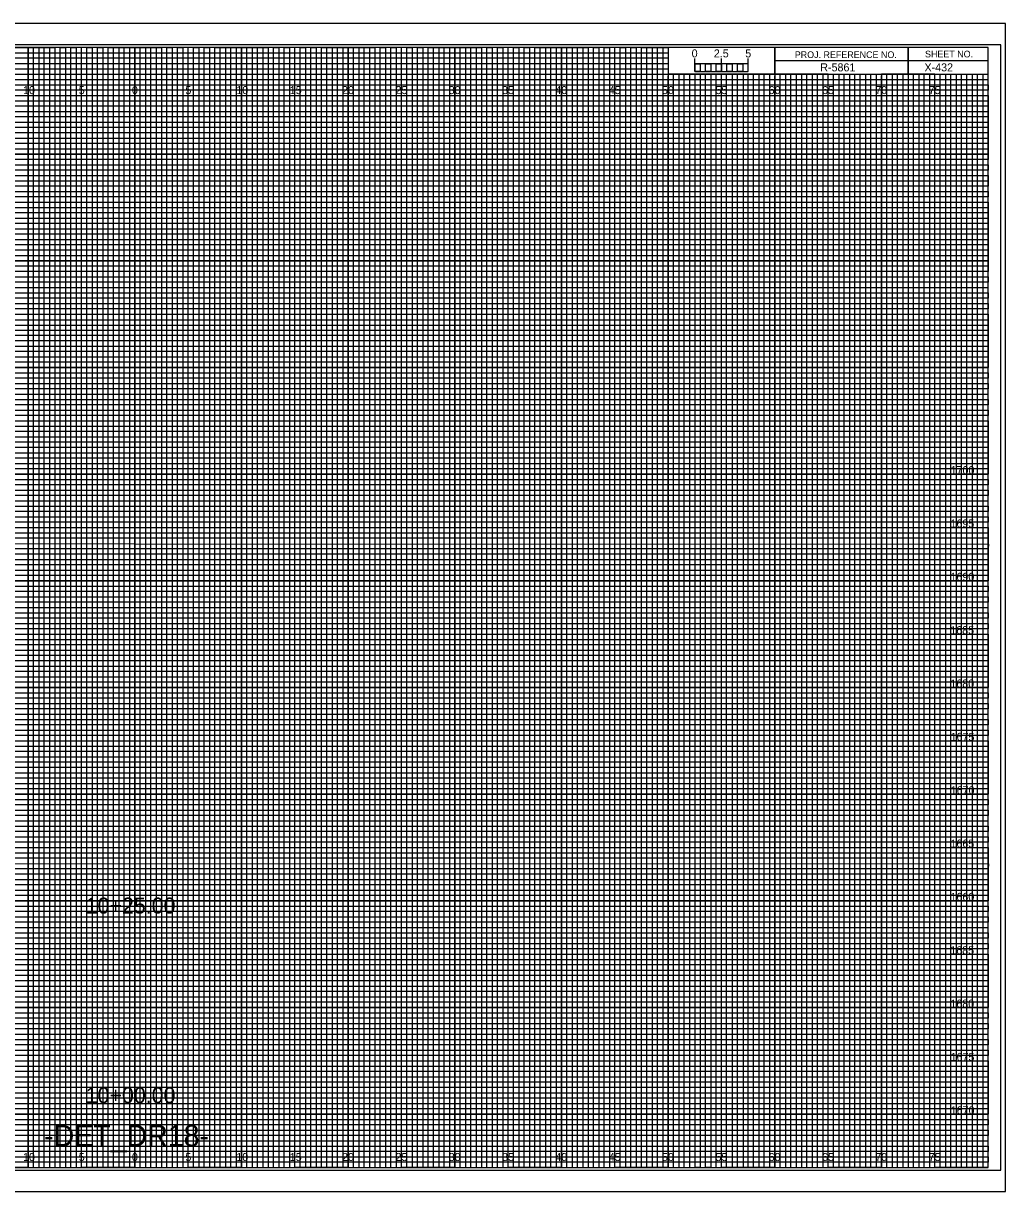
# Model space of a CAD drawing. Extents: x -7 to 162, y -2 to 437.
# Drawn here: x 69.5 to 161.7, y -2.3 to 107.3 of the extents above; entities that cross this region are included whole.
import ezdxf

# ---------------------------------------------------------------- set-up
doc = ezdxf.new("R2010")
doc.units = 0
for name, color, linetype in [('Prop Horizontal Alignment', 7, 'Continuous'), ('Prop XS Alignment Label', 7, 'Continuous'), ('Prop XS Bar Scale Labels', 7, 'Continuous'), ('Prop XS Project Number', 7, 'Continuous'), ('Prop XS Sheet Number', 7, 'Continuous'), ('Raster_Level_0', 7, 'Continuous'), ('Scratch_Level_3', 7, 'Continuous'), ('Sheet Cross Section CELL', 7, 'Continuous'), ('Sheet Cross Section Grid Major CELL', 7, 'Continuous'), ('Sheet Cross Section Grid Middle CELL', 7, 'Continuous'), ('Sheet Cross Section Grid Minor 1 CELL', 7, 'Continuous'), ('Sheet Cross Section Grid Minor 2 CELL', 7, 'Continuous'), ('Sheet Cross Section Scale CELL', 7, 'Continuous'), ('Sheet Cutting Line CELL', 7, 'Continuous'), ('Sheet DOT Grid CELL', 7, 'Continuous'), ('Sheet Plot Border Inside CELL', 7, 'Continuous'), ('Sheet Plot Border Outside CELL', 7, 'Continuous')]:
    doc.layers.add(name, color=color, linetype=linetype)

msp = doc.modelspace()

# ---------------------------------------------------------------- linework, layer by layer
at = {"layer": 'Sheet Cross Section CELL'}
for p, q in [((152.5, 105), (152.5, 102.5)), ((152.5, 102.5), (152.5, 105)), ((160, 103.75), (140, 103.75)), ((140, 103.75), (140, 102.5)), ((140, 102.5), (160, 102.5))]:
    msp.add_line(p, q, dxfattribs=at)
for points in [[(160, 105), (0, 105), (0, 0), (160, 0)], [(140, 105), (130, 105), (130, 102.52), (140, 102.52)], [(160, 105), (140, 105), (140, 102.5), (160, 102.5)]]:
    msp.add_lwpolyline(points, close=True, dxfattribs=at)
at = {"layer": 'Sheet Cross Section Grid Major CELL'}
for p, q in [((75, 105), (70, 105)), ((70, 105), (70, 0)), ((75, 0), (75, 105)), ((85, 105), (80, 105)), ((80, 105), (80, 0)), ((85, 0), (85, 105)), ((95, 105), (90, 105)), ((90, 105), (90, 0)), ((95, 0), (95, 105)), ((105, 105), (100, 105)), ((100, 105), (100, 0)), ((105, 0), (105, 105)), ((115, 105), (110, 105)), ((110, 105), (110, 0)), ((115, 0), (115, 105)), ((125, 105), (120, 105)), ((120, 105), (120, 0)), ((125, 0), (125, 105)), ((130, 105), (130, 0)), ((135, 0), (135, 102.5)), ((145, 102.5), (140, 102.5)), ((140, 102.5), (140, 0)), ((145, 0), (145, 102.5)), ((155, 102.5), (150, 102.5)), ((150, 102.5), (150, 0)), ((155, 0), (155, 102.5)), ((70, 0), (65, 0)), ((80, 0), (75, 0)), ((90, 0), (85, 0)), ((100, 0), (95, 0)), ((110, 0), (105, 0)), ((120, 0), (115, 0)), ((130, 0), (125, 0)), ((140, 0), (135, 0)), ((150, 0), (145, 0)), ((160, 0), (155, 0)), ((160, 0), (160, 0))]:
    msp.add_line(p, q, dxfattribs=at)
for points in [[(0, 100), (160, 100), (160, 95), (0, 95)], [(0, 90), (160, 90), (160, 85), (0, 85)], [(0, 80), (160, 80), (160, 75), (0, 75)], [(0, 70), (160, 70), (160, 65), (0, 65)], [(0, 60), (160, 60), (160, 55), (0, 55)], [(0, 50), (160, 50), (160, 45), (0, 45)], [(0, 40), (160, 40), (160, 35), (0, 35)], [(0, 30), (160, 30), (160, 25), (0, 25)], [(0, 20), (160, 20), (160, 15), (0, 15)], [(0, 10), (160, 10), (160, 5), (0, 5)]]:
    msp.add_lwpolyline(points, dxfattribs=at)
at = {"layer": 'Sheet Cross Section Grid Middle CELL'}
for points in [[(67.5, 105), (72.5, 105), (72.5, 0), (77.5, 0), (77.5, 105), (82.5, 105), (82.5, 0), (87.5, 0), (87.5, 105), (92.5, 105), (92.5, 0), (97.5, 0), (97.5, 105), (102.5, 105), (102.5, 0), (107.5, 0), (107.5, 105), (112.5, 105), (112.5, 0), (117.5, 0), (117.5, 105), (122.5, 105), (122.5, 0), (127.5, 0), (127.5, 105), (129.97, 105), (130, 105), (130, 102.5), (132.5, 102.5), (132.5, 0), (137.5, 0), (137.5, 102.5), (142.5, 102.5), (142.5, 0), (147.5, 0), (147.5, 102.5), (152.5, 102.5), (152.5, 0), (157.5, 0), (157.5, 102.5)], [(0, 102.5), (137.5, 102.5)], [(0, 92.5), (160, 92.5), (160, 97.5), (0, 97.5)], [(0, 82.5), (160, 82.5), (160, 87.5), (0, 87.5)], [(0, 72.5), (160, 72.5), (160, 77.5), (0, 77.5)], [(0, 62.5), (160, 62.5), (160, 67.5), (0, 67.5)], [(0, 52.5), (160, 52.5), (160, 57.5), (0, 57.5)], [(0, 42.5), (160, 42.5), (160, 47.5), (0, 47.5)], [(0, 32.5), (160, 32.5), (160, 37.5), (0, 37.5)], [(0, 22.5), (160, 22.5), (160, 27.5), (0, 27.5)], [(0, 12.5), (160, 12.5), (160, 17.5), (0, 17.5)], [(0, 2.5), (160, 2.5), (160, 7.5), (0, 7.5)]]:
    msp.add_lwpolyline(points, dxfattribs=at)
at = {"layer": 'Sheet Cross Section Grid Minor 1 CELL'}
for p, q in [((0, 104.5), (130, 104.5)), ((130, 104.5), (130, 103.99)), ((130, 103.99), (0, 103.99)), ((0, 103.5), (130, 103.5)), ((130, 102.95), (0, 102.95)), ((130, 103.5), (130, 102.95)), ((0, 102), (160, 102))]:
    msp.add_line(p, q, dxfattribs=at)
for points in [[(0, 101.5), (135, 101.5), (160, 101.5), (160, 101), (0, 101)], [(0, 100.5), (160, 100.5), (160, 99.5), (0, 99.5)], [(0, 99), (160, 99), (160, 98.5), (0, 98.49)], [(0, 98), (160, 98), (160, 97), (0, 97)], [(0, 96.5), (160, 96.5), (160, 96), (0, 96)], [(0, 95.5), (160, 95.5), (160, 94.5), (0, 94.5)], [(0, 94), (160, 94), (160, 93.5), (0, 93.5)], [(0, 93), (160, 93), (160, 92), (0, 92)], [(0, 91.5), (160, 91.5), (160, 91), (0, 91)], [(0, 90.5), (160, 90.5), (160, 89.5), (0, 89.5)], [(0, 89), (160, 89), (160, 88.5), (0, 88.5)], [(0, 88), (160, 88), (160, 86.98), (160, 86.5), (160, 86), (0, 86)], [(0, 87), (160, 87), (160, 86.5), (0, 86.5)], [(0, 85.5), (160, 85.5), (160, 84.5), (0, 84.52)], [(0, 84.52), (160, 84.5), (160, 84), (0, 84)], [(0, 83.5), (160, 83.5), (160, 83), (0, 83)], [(0, 82), (160, 82), (160, 81.5), (0, 81.5)], [(0, 81), (160, 81), (160, 80.5), (0, 80.5)], [(-0.04, 79.45), (160, 79.45), (160, 78.94), (-0.04, 78.94)], [(0, 78.5), (160, 78.5), (160, 78), (0, 78)], [(0, 77), (160, 77), (160, 76.5), (0, 76.5)], [(0, 76), (160, 76), (160, 75.5), (0, 75.5)], [(0, 74.5), (160, 74.5), (160, 74), (0, 74)], [(0, 73.5), (160, 73.5), (160, 73), (0, 73)], [(0, 72), (160, 72), (160, 71.5), (0, 71.5)], [(0, 71), (160, 71), (160, 70.5), (0, 70.5)], [(0, 69.5), (160, 69.5), (160, 68.99), (0, 69)], [(0, 68.5), (160, 68.5), (160, 68), (0, 68)], [(0, 67), (160, 67), (160, 66.5), (0, 66.5)], [(0, 66), (160, 66), (160, 65.5), (0, 65.5)], [(0, 64.5), (160, 64.5), (160, 64), (0, 64)], [(0, 63.5), (160, 63.5), (160, 63), (0, 63)], [(0, 62), (160, 62), (160, 61.5), (0, 61.5)], [(0, 61), (160, 61), (160, 60.5), (0, 60.5)], [(0, 59.5), (160, 59.5), (160, 59), (0, 59)], [(0, 58.5), (160.03, 58.45), (160, 58), (0, 58)], [(0, 57), (160, 57), (160, 56.5), (0, 56.5)], [(0, 56), (160, 56), (160, 55.5), (0, 55.5)], [(0, 54.5), (160, 54.5), (160, 54), (0, 54)], [(0, 53.5), (160, 53.5), (160, 53), (0, 53)], [(0, 52), (160, 52), (160, 51.5), (0, 51.5)], [(0, 51), (160, 51), (160, 50.5), (0, 50.5)], [(0, 49.5), (160, 49.5), (160, 49), (0, 49)], [(0, 48.5), (160, 48.5), (160, 48), (0, 48)], [(0, 47), (160, 47), (160, 46.5), (0, 46.5)], [(0, 46), (160, 46), (160, 45.5), (0, 45.5)], [(0, 44.5), (160, 44.5), (160, 44), (0, 44)], [(0, 43.5), (160, 43.5), (160, 43), (0, 43)], [(0, 42), (160, 42), (160, 41.5), (0, 41.5)], [(0, 41), (160, 41), (160, 40.5), (0, 40.5)], [(0, 39.5), (160, 39.5), (160, 38.99), (0, 39)], [(0, 38.5), (160, 38.5), (160, 38), (0, 38)], [(0, 37), (160, 37), (160, 36.5), (0, 36.5)], [(0, 36), (160, 36), (160, 35.5), (0, 35.5)], [(0, 34.5), (160, 34.5), (160, 34), (0, 34)], [(0, 33.5), (160, 33.5), (160, 33), (0, 33)], [(0, 32), (160, 32), (160, 31.5), (0, 31.5)], [(0, 31), (160, 31), (160, 30.5), (0, 30.5)], [(0, 29.5), (160, 29.5), (160, 29), (0, 29)], [(0, 28.5), (160.03, 28.46), (160, 28), (0, 28)], [(0, 27), (160, 27), (160, 26.5), (0, 26.5)], [(0, 26), (160, 26), (160, 25.5), (0, 25.5)], [(0, 24.5), (160, 24.5), (160, 24), (0, 24)], [(0, 23.5), (160, 23.5), (160, 23), (0, 23)], [(0, 22), (160, 22), (160, 21.5), (0, 21.5)], [(0, 21), (160, 21), (160, 20.5), (0, 20.5)], [(0, 19.5), (160, 19.5), (160, 19), (0, 19)], [(0, 18.5), (160, 18.5), (160, 18), (0, 18)], [(0, 17), (160, 17), (160, 16.5), (0, 16.5)], [(0, 16), (160, 16), (160, 15.5), (0, 15.5)], [(0, 14.5), (160, 14.5), (160, 14), (0, 14)], [(0, 13.5), (160, 13.5), (160, 13), (0, 13)], [(0, 12), (160, 12), (160, 11.5), (0, 11.5)], [(0, 11), (160, 11), (160, 10.5), (0, 10.5)], [(0, 9.5), (160, 9.5), (160, 9), (0, 9)], [(0, 8.5), (160, 8.5), (160, 8), (0, 8)], [(0, 7), (160, 7), (160, 6.5), (0, 6.5)], [(0, 6), (160, 6), (160, 5.5), (0, 5.5)], [(0, 4.5), (160, 4.5), (160, 4), (0, 4)], [(0, 3.5), (160, 3.5), (160, 3), (0, 3)], [(0, 2), (160, 2), (160, 1.5), (0, 1.5)], [(0, 1), (160, 1), (160, 0.5), (0, 0.5)]]:
    msp.add_lwpolyline(points, dxfattribs=at)
at = {"layer": 'Sheet Cross Section Grid Minor 2 CELL'}
for p, q in [((133.5, 102.5), (133, 102.5)), ((133, 102.5), (133, 0)), ((133.5, 0), (133.5, 102.5)), ((134.5, 102.5), (134, 102.5)), ((134, 102.5), (134, 0)), ((134.5, 0), (134.5, 102.5)), ((133, 0), (132.5, 0)), ((134, 0), (133.5, 0))]:
    msp.add_line(p, q, dxfattribs=at)
for points in [[(70, 0), (70.5, 0), (70.5, 105), (71, 105), (71, 0)], [(71, 0), (71.5, 0), (71.5, 105), (72, 105), (72, 0)], [(72.5, 0), (73, 0), (73, 105), (73.5, 105), (73.5, 0)], [(73.5, 0), (74, 0), (74, 105), (74.5, 105), (74.5, 0)], [(75, 0), (75.5, 0), (75.5, 105), (76, 105), (76, 0)], [(76, 0), (76.5, 0), (76.5, 105), (77, 105), (77, 0)], [(77.5, 0), (78, 0), (78, 105), (78.5, 105), (78.5, 0)], [(78.5, 0), (79, 0), (79, 105), (79.5, 105), (79.5, 0)], [(80, 0), (80.5, 0), (80.5, 105), (81, 105), (81, 0)], [(81, 0), (81.5, 0), (81.5, 105), (82, 105), (82, 0)], [(82.5, 0), (83, 0), (83, 105), (83.5, 105), (83.5, 0)], [(83.5, 0), (84, 0), (84, 105), (84.5, 105), (84.5, 0)], [(85, 0), (85.5, 0), (85.5, 105), (86, 105), (86, 0)], [(86, 0), (86.5, 0), (86.5, 105), (87, 105), (87, 0)], [(87.5, 0), (88, 0), (88, 105), (88.5, 105), (88.5, 0)], [(88.5, 0), (89, 0), (89, 105), (89.5, 105), (89.5, 0)], [(90, 0), (90.5, 0), (90.5, 105), (91, 105), (91, 0)], [(91, 0), (91.5, 0), (91.5, 105), (92, 105), (92, 0)], [(92.5, 0), (93, 0), (93, 105), (93.5, 105), (93.5, 0)], [(93.5, 0), (94, 0), (94, 105), (94.5, 105), (94.5, 0)], [(95, 0), (95.5, 0), (95.5, 105), (96, 105), (96, 0)], [(96, 0), (96.5, 0), (96.5, 105), (97, 105), (97, 0)], [(97.5, 0), (98, 0), (98, 105), (98.5, 105), (98.5, 0)], [(98.5, 0), (99, 0), (99, 105), (99.5, 105), (99.5, 0)], [(100, 0), (100.5, 0), (100.5, 105), (101, 105), (101, 0)], [(101, 0), (101.5, 0), (101.5, 105), (102, 105), (102, 0)], [(102.5, 0), (103, 0), (103, 105), (103.5, 105), (103.5, 0)], [(103.5, 0), (104, 0), (104, 105), (104.5, 105), (104.5, 0)], [(105, 0), (105.5, 0), (105.5, 105), (106, 105), (106, 0)], [(106, 0), (106.5, 0), (106.5, 105), (107, 105), (107, 0)], [(107.5, 0), (108, 0), (108, 105), (108.5, 105), (108.5, 0)], [(108.5, 0), (109, 0), (109, 105), (109.5, 105), (109.5, 0)], [(110, 0), (110.5, 0), (110.5, 105), (111, 105), (111, 0)], [(111, 0), (111.5, 0), (111.5, 105), (112, 105), (112, 0)], [(112.5, 0), (113, 0), (113, 105), (113.5, 105), (113.5, 0)], [(113.5, 0), (114, 0), (114, 105), (114.5, 105), (114.5, 0)], [(115, 0), (115.5, 0), (115.5, 105), (116, 105), (116, 0)], [(116, 0), (116.5, 0), (116.5, 105), (117, 105), (117, 0)], [(117.5, 0), (118, 0), (118, 105), (118.5, 105), (118.5, 0)], [(118.5, 0), (119, 0), (119, 105), (119.5, 105), (119.5, 0)], [(120, 0), (120.5, 0), (120.5, 105), (121, 105), (121, 0)], [(121, 0), (121.5, 0), (121.5, 105), (122, 105), (122, 0)], [(122.5, 0), (123, 0), (123, 105), (123.5, 105), (123.5, 0)], [(123.5, 0), (124, 0), (124, 105), (124.5, 105), (124.5, 0)], [(125, 0), (125.5, 0), (125.5, 105), (126, 105), (126, 0)], [(126, 0), (126.5, 0), (126.5, 105), (127, 105), (127, 0)], [(127.5, 0), (128, 0), (128, 105), (128.5, 105), (128.5, 0)], [(128.5, 0), (129, 0), (129, 105), (129.5, 105), (129.5, 0)], [(130, 0), (130.5, 0), (130.5, 102.5), (131.01, 102.5), (131.01, 0)], [(131, 0), (131.5, 0), (131.5, 102.5), (132, 102.5), (132, 0)], [(135, 0), (135.49, 0), (135.49, 102.5), (136, 102.5), (136, 0)], [(136, 0), (136.5, 0), (136.5, 102.5), (137.03, 102.5), (137.03, 0)], [(137.5, 0), (138, 0), (138, 102.5), (138.5, 102.5), (138.5, 0)], [(138.5, 0), (139, 0), (139, 102.5), (139.5, 102.5), (139.5, 0)], [(140, 0), (140.5, 0), (140.5, 102.5), (141, 102.5), (141, 0)], [(141, 0), (141.5, 0), (141.5, 102.5), (142, 102.5), (142, 0)], [(142.5, 0), (143, 0), (143, 102.5), (143.5, 102.5), (143.5, 0)], [(143.5, 0), (144, 0), (144, 102.5), (144.5, 102.5), (144.5, 0)], [(145, 0), (145.5, 0), (145.5, 102.5), (146, 102.5), (146, 0)], [(146, 0), (146.5, 0), (146.5, 102.5), (147, 102.5), (147, 0)], [(147.5, 0), (148, 0), (148, 102.5), (148.5, 102.5), (148.5, 0)], [(148.5, 0), (149, 0), (149, 102.5), (149.5, 102.5), (149.5, 0)], [(150, 0), (150.5, 0), (150.5, 102.5), (151, 102.5), (151, 0)], [(151, 0), (151.5, 0), (151.5, 102.5), (152, 102.5), (152, 0)], [(152.5, 0), (153, 0), (153, 102.5), (153.5, 102.5), (153.5, 0)], [(153.5, 0), (154, 0), (154, 102.5), (154.5, 102.5), (154.5, 0)], [(155, 0), (155.5, 0), (155.5, 102.5), (156, 102.5), (156, 0)], [(156, 0), (156.5, 0), (156.5, 102.5), (157, 102.5), (157, 0)], [(157.5, 0), (158, 0), (158, 102.5), (158.5, 102.5), (158.5, 0)], [(158.5, 0), (159, 0), (159, 102.5), (159.5, 102.5), (159.5, 0)]]:
    msp.add_lwpolyline(points, dxfattribs=at)
at = {"layer": 'Sheet Cross Section Scale CELL'}
for p, q in [((132.5, 102.75), (132.5, 103.95)), ((132.5, 103.45), (132.5, 103.95)), ((135, 102.75), (135, 103.95)), ((137.5, 102.75), (137.5, 103.95)), ((137.5, 103.45), (137.5, 103.95))]:
    msp.add_line(p, q, dxfattribs=at)
for points in [[(137.5, 103.45), (132.5, 103.45), (132.5, 102.75), (137.5, 102.75)], [(132.5, 103.45), (133, 103.45), (133, 102.75), (132.5, 102.75)], [(133.5, 103.45), (134, 103.45), (134, 102.75), (133.5, 102.75)], [(134.5, 103.45), (135, 103.45), (135, 102.75), (134.5, 102.75)], [(135.5, 103.45), (136, 103.45), (136, 102.75), (135.5, 102.75)], [(136.5, 103.45), (137, 103.45), (137, 102.75), (136.5, 102.75)]]:
    msp.add_lwpolyline(points, close=True, dxfattribs=at)
at = {"layer": 'Sheet Cutting Line CELL'}
for p, q in [((161.65, 107.25), (-6.7, 107.25)), ((-6.7, -2.25), (161.65, -2.25))]:
    msp.add_line(p, q, dxfattribs=at)
at = {"layer": 'Sheet DOT Grid CELL'}
for p, q in [((70, 0), (70, 105)), ((75, 0), (75, 105)), ((80, 0), (80, 105)), ((85, 0), (85, 105)), ((90, 0), (90, 105)), ((95, 0), (95, 105)), ((100, 0), (100, 105)), ((105, 0), (105, 105)), ((110, 0), (110, 105)), ((115, 0), (115, 105)), ((120, 0), (120, 105)), ((125, 0), (125, 105)), ((130, 0), (130, 102.34)), ((135, 0), (135, 102.34)), ((140, 0), (140, 102.34)), ((145, 0), (145, 102.34)), ((150, 0), (150, 102.34)), ((155, 0), (155, 102.34)), ((0, 100), (160, 100)), ((0, 95), (160, 95)), ((0, 90), (160, 90)), ((0, 85), (160, 85)), ((0, 80), (160, 80)), ((0, 75), (160, 75)), ((0, 70), (160, 70)), ((0, 65), (160, 65)), ((0, 60), (160, 60)), ((0, 55), (160, 55)), ((0, 50), (160, 50)), ((0, 45), (160, 45)), ((0, 40), (160, 40)), ((0, 35), (160, 35)), ((0, 30), (160, 30)), ((0, 25), (160, 25)), ((0, 20), (160, 20)), ((0, 15), (160, 15)), ((0, 10), (160, 10)), ((0, 5), (160, 5))]:
    msp.add_line(p, q, dxfattribs=at)
at = {"layer": 'Sheet Plot Border Inside CELL'}
msp.add_lwpolyline([(-5.4, -0.25), (161.2, -0.25), (161.2, 105.25), (-5.4, 105.25)], close=True, dxfattribs=at)
at = {"layer": 'Sheet Plot Border Outside CELL'}
msp.add_lwpolyline([(-6.7, -2.25), (161.65, -2.25), (161.65, 107.25), (-6.7, 107.25)], close=True, dxfattribs=at)

# ---------------------------------------------------------------- texts
at = {"layer": 'Prop Horizontal Alignment'}
for s, p in [('10+25.00', (75.39, 23.81)), ('10+00.00', (75.39, 6.04))]:
    msp.add_text(s, height=1.5, dxfattribs=at).set_placement(p)
at = {"layer": 'Prop XS Alignment Label'}
msp.add_text('-DET_DR18-', height=2, dxfattribs=at).set_placement((71.5, 2))
at = {"layer": 'Prop XS Bar Scale Labels'}
for s, p in [('2.5', (134.29, 104.06)), ('5', (137.24, 104.06))]:
    msp.add_text(s, height=0.75, dxfattribs=at).set_placement(p)
at = {"layer": 'Prop XS Project Number'}
msp.add_text('R-5861', height=0.75, dxfattribs=at).set_placement((144.27, 102.75))
at = {"layer": 'Prop XS Sheet Number'}
msp.add_text('X-432', height=0.75, dxfattribs=at).set_placement((154.04, 102.75))
at = {"layer": 'Raster_Level_0'}
for s, p in [('10', (69.52, 100.62)), ('5', (74.74, 100.62)), ('0', (79.73, 100.62)), ('0', (79.73, 100.62)), ('5', (84.74, 100.62)), ('10', (89.52, 100.62)), ('15', (94.53, 100.62)), ('20', (99.43, 100.62)), ('25', (104.44, 100.62)), ('30', (109.43, 100.62)), ('35', (114.44, 100.62)), ('40', (119.43, 100.62)), ('45', (124.44, 100.62)), ('50', (129.43, 100.62)), ('55', (134.44, 100.62)), ('60', (139.43, 100.62)), ('65', (144.44, 100.62)), ('70', (149.43, 100.62)), ('75', (154.44, 100.62)), ('10', (69.52, 0.62)), ('5', (74.74, 0.62)), ('0', (79.73, 0.62)), ('0', (79.73, 0.62)), ('5', (84.74, 0.62)), ('10', (89.52, 0.62)), ('15', (94.53, 0.62)), ('20', (99.43, 0.62)), ('25', (104.44, 0.62)), ('30', (109.43, 0.62)), ('35', (114.44, 0.62)), ('40', (119.43, 0.62)), ('45', (124.44, 0.62)), ('50', (129.43, 0.62)), ('55', (134.44, 0.62)), ('60', (139.43, 0.62)), ('65', (144.44, 0.62)), ('70', (149.43, 0.62)), ('75', (154.44, 0.62))]:
    msp.add_text(s, height=0.75, dxfattribs=at).set_placement(p)
at = {"layer": 'Scratch_Level_3'}
for s, p in [('1700', (156.49, 65)), ('1695', (156.48, 60)), ('1690', (156.48, 55)), ('1685', (156.46, 50)), ('1680', (156.47, 45)), ('1675', (156.49, 40)), ('1670', (156.5, 35)), ('1665', (156.48, 30)), ('1660', (156.48, 25)), ('1685', (156.46, 20)), ('1680', (156.47, 15)), ('1675', (156.49, 10)), ('1670', (156.5, 5))]:
    msp.add_text(s, height=0.75, dxfattribs=at).set_placement(p)
at = {"layer": 'Sheet Cross Section CELL'}
for s, p in [('PROJ. REFERENCE NO.', (141.88, 104)), ('SHEET NO.', (154.09, 104.06))]:
    msp.add_text(s, height=0.625, dxfattribs=at).set_placement(p)
at = {"layer": 'Sheet Cross Section Scale CELL'}
msp.add_text('0', height=0.75, dxfattribs=at).set_placement((132.21, 104.06))

doc.saveas('drawing.dxf')
